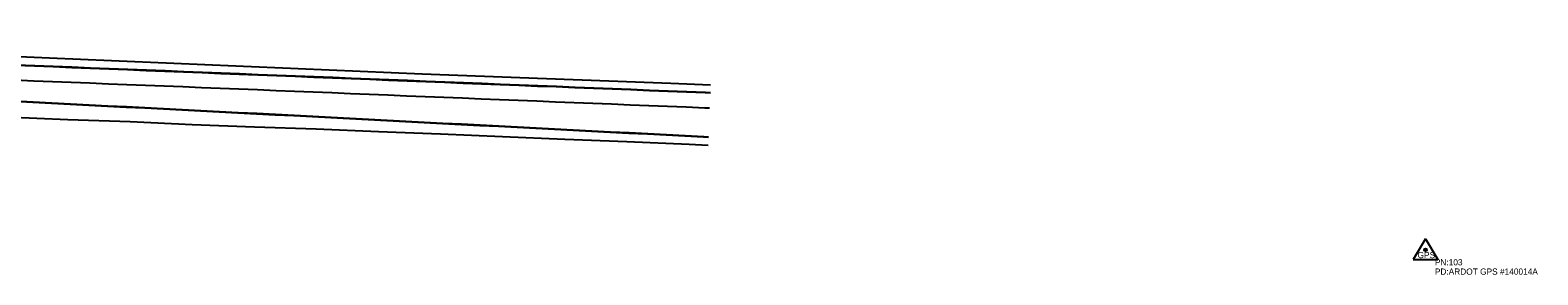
# Model space of a CAD drawing. Extents: x 878399 to 889864, y 1564003 to 1567413.
# Drawn here: x 888651 to 889864, y 1564244 to 1564441 of the extents above; entities that cross this region are included whole.
import ezdxf

# ---------------------------------------------------------------- set-up
doc = ezdxf.new("R2010")
doc.units = 0
for name, color, linetype in [('S_EDGE_PAVEMENT', 7, 'Continuous'), ('S_PAVEMENT_CROWN', 7, 'Continuous'), ('S_PRIMARY_CTL', 7, 'Continuous'), ('S_PRIMARY_CTL_ANNOT', 7, 'Continuous'), ('S_SHOULDER', 7, 'Continuous')]:
    doc.layers.add(name, color=color, linetype=linetype)

msp = doc.modelspace()

# ---------------------------------------------------------------- linework, layer by layer
at = {"layer": 'S_EDGE_PAVEMENT'}
for points in [[(888639.6, 1564412.6), (888654.6, 1564412), (888669.6, 1564411.4), (888684.6, 1564410.8), (888699.5, 1564410.2), (888714.5, 1564409.6), (888729.5, 1564409), (888744.5, 1564408.4), (888759.5, 1564407.8), (888774.5, 1564407.2), (888789.5, 1564406.6), (888804.5, 1564406), (888819.4, 1564405.4), (888834.4, 1564404.8), (888849.4, 1564404.2), (888864.4, 1564403.6), (888879.4, 1564403), (888894.4, 1564402.4), (888909.4, 1564401.8), (888924.4, 1564401.2), (888939.4, 1564400.6), (888954.4, 1564400), (888969.4, 1564399.4), (888984.4, 1564398.8), (888999.4, 1564398.2), (889014.3, 1564397.6), (889029.3, 1564397), (889044.3, 1564396.4), (889059.3, 1564395.8), (889074.3, 1564395.3), (889089.3, 1564394.7), (889104.3, 1564394.1), (889119.3, 1564393.5), (889134.2, 1564392.9), (889149.2, 1564392.3), (889164.2, 1564391.7), (889179.2, 1564391.1), (889194.2, 1564390.5), (889198.2, 1564390.3)], [(888639.8, 1564412.9), (888654.8, 1564412.3), (888669.8, 1564411.7), (888684.8, 1564411.1), (888699.8, 1564410.5), (888714.7, 1564409.9), (888729.7, 1564409.3), (888744.7, 1564408.7), (888759.7, 1564408.2), (888774.7, 1564407.6), (888789.7, 1564407), (888804.7, 1564406.4), (888819.6, 1564405.8), (888834.6, 1564405.2), (888849.6, 1564404.6), (888864.6, 1564404), (888879.6, 1564403.4), (888894.6, 1564402.8), (888909.6, 1564402.2), (888924.6, 1564401.6), (888939.6, 1564401), (888954.6, 1564400.4), (888969.6, 1564399.8), (888984.6, 1564399.2), (888999.6, 1564398.6), (889014.5, 1564398), (889029.5, 1564397.4), (889044.5, 1564396.8), (889059.5, 1564396.2), (889074.5, 1564395.6), (889089.5, 1564395), (889104.5, 1564394.4), (889119.5, 1564393.8), (889134.4, 1564393.2), (889149.4, 1564392.6), (889164.4, 1564392), (889179.4, 1564391.4), (889194.4, 1564390.8), (889198.4, 1564390.6)], [(888638.4, 1564383.6), (888653.4, 1564382.8), (888668.4, 1564382), (888683.4, 1564381.3), (888698.4, 1564380.5), (888713.3, 1564379.7), (888728.3, 1564378.9), (888743.3, 1564378.2), (888758.3, 1564377.4), (888773.3, 1564376.6), (888788.3, 1564375.8), (888803.3, 1564375.1), (888818.2, 1564374.3), (888833.2, 1564373.5), (888848.2, 1564372.7), (888863.2, 1564372), (888878.2, 1564371.2), (888893, 1564370.4), (888908, 1564369.6), (888923, 1564368.9), (888938, 1564368.1), (888953, 1564367.3), (888968, 1564366.6), (888982.9, 1564365.8), (888997.9, 1564365), (889012.9, 1564364.2), (889027.9, 1564363.5), (889042.9, 1564362.7), (889057.9, 1564361.9), (889072.9, 1564361.1), (889087.8, 1564360.4), (889102.8, 1564359.6), (889117.8, 1564358.8), (889132.8, 1564358), (889147.8, 1564357.3), (889162.7, 1564356.5), (889177.7, 1564355.7), (889192.7, 1564354.9), (889196.7, 1564354.7)], [(888638.6, 1564383.9), (888653.6, 1564383.1), (888668.6, 1564382.4), (888683.6, 1564381.6), (888698.6, 1564380.8), (888713.6, 1564380), (888728.6, 1564379.3), (888743.5, 1564378.5), (888758.5, 1564377.7), (888773.5, 1564376.9), (888788.5, 1564376.2), (888803.5, 1564375.4), (888818.4, 1564374.6), (888833.4, 1564373.9), (888848.4, 1564373.1), (888863.4, 1564372.3), (888878.4, 1564371.5), (888893.2, 1564370.8), (888908.2, 1564370), (888923.2, 1564369.2), (888938.2, 1564368.4), (888953.2, 1564367.7), (888968.2, 1564366.9), (888983.1, 1564366.1), (888998.1, 1564365.3), (889013.1, 1564364.6), (889028.1, 1564363.8), (889043.1, 1564363), (889058.1, 1564362.2), (889073, 1564361.5), (889088, 1564360.7), (889103, 1564359.9), (889118, 1564359.1), (889133, 1564358.4), (889148, 1564357.6), (889162.9, 1564356.8), (889177.9, 1564356.1), (889192.9, 1564355.3), (889196.9, 1564355.1)]]:
    msp.add_lwpolyline(points, dxfattribs=at)
at = {"layer": 'S_PAVEMENT_CROWN'}
msp.add_lwpolyline([(888639.1, 1564400.7), (888654.1, 1564400.1), (888669.1, 1564399.5), (888684.1, 1564398.9), (888699.1, 1564398.3), (888714.1, 1564397.7), (888729, 1564397.1), (888744, 1564396.5), (888759, 1564395.9), (888774, 1564395.3), (888789, 1564394.7), (888804, 1564394.1), (888819, 1564393.5), (888834, 1564392.9), (888849, 1564392.3), (888863.9, 1564391.7), (888878.9, 1564391.1), (888893.9, 1564390.5), (888908.9, 1564389.9), (888923.9, 1564389.3), (888938.9, 1564388.7), (888953.9, 1564388), (888968.9, 1564387.4), (888983.8, 1564386.8), (888998.8, 1564386.2), (889013.8, 1564385.6), (889028.8, 1564385), (889043.8, 1564384.4), (889058.8, 1564383.8), (889073.8, 1564383.2), (889088.8, 1564382.6), (889103.8, 1564382), (889118.7, 1564381.4), (889133.7, 1564380.8), (889148.7, 1564380.2), (889163.7, 1564379.6), (889178.7, 1564379), (889193.7, 1564378.4), (889197.7, 1564378.3)], dxfattribs=at)
at = {"layer": 'S_PRIMARY_CTL'}
for p, q in [((889773.5, 1564272.9), (889763.5, 1564256.4)), ((889773.5, 1564272.9), (889783.3, 1564256.4)), ((889763.5, 1564256.4), (889783.3, 1564256.4))]:
    msp.add_line(p, q, dxfattribs=at)
for radius in [1.04, 0.609, 0.344]:
    msp.add_circle((889773.5, 1564264.2), radius, dxfattribs=at)
at = {"layer": 'S_SHOULDER'}
for points in [[(888117.4, 1564440.7), (888167.4, 1564439.2), (888217.3, 1564437), (888267.1, 1564434.9), (888317, 1564432.5), (888367, 1564430.9), (888417, 1564428.6), (888466.9, 1564426.3), (888516.9, 1564424.4), (888566.9, 1564422.3), (888616.8, 1564420.6), (888666.8, 1564418.5), (888716.7, 1564416.3), (888766.7, 1564414.1), (888816.6, 1564411.9), (888866.6, 1564409.9), (888916.6, 1564407.7), (888966.6, 1564405.7), (889016.6, 1564403.8), (889066.5, 1564401.8), (889116.5, 1564400), (889166.4, 1564398), (889198.5, 1564396.9)], [(888631.6, 1564371), (888681.5, 1564368.9), (888731.5, 1564367.3), (888781.5, 1564365), (888831.5, 1564363.1), (888881.3, 1564361.5), (888931.3, 1564359.4), (888981.2, 1564357.3), (889031.2, 1564355.3), (889081.2, 1564353.2), (889131.1, 1564351.2), (889181.1, 1564349.1), (889196.4, 1564348.4)]]:
    msp.add_lwpolyline(points, dxfattribs=at)

# ---------------------------------------------------------------- texts
at = {"layer": 'S_PRIMARY_CTL'}
msp.add_text('GPS', height=5, rotation=360, dxfattribs=at).set_placement((889767.1, 1564257.5))
at = {"layer": 'S_PRIMARY_CTL_ANNOT'}
for s, p in [('PN:103', (889781, 1564251.7)), ('PD:ARDOT GPS #140014A', (889781, 1564244.2))]:
    msp.add_text(s, height=5, dxfattribs=at).set_placement(p)

doc.saveas('drawing.dxf')
